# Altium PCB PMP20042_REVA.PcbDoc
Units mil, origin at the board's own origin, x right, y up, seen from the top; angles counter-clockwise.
Board outline 2260 x 1800 mil, 4 copper layers (Top Layer, Signal Layer 1, Signal Layer 2, Bottom Layer), stack 61.2 mil thick; 80 components, 41 nets, 195 pads, 85 vias.
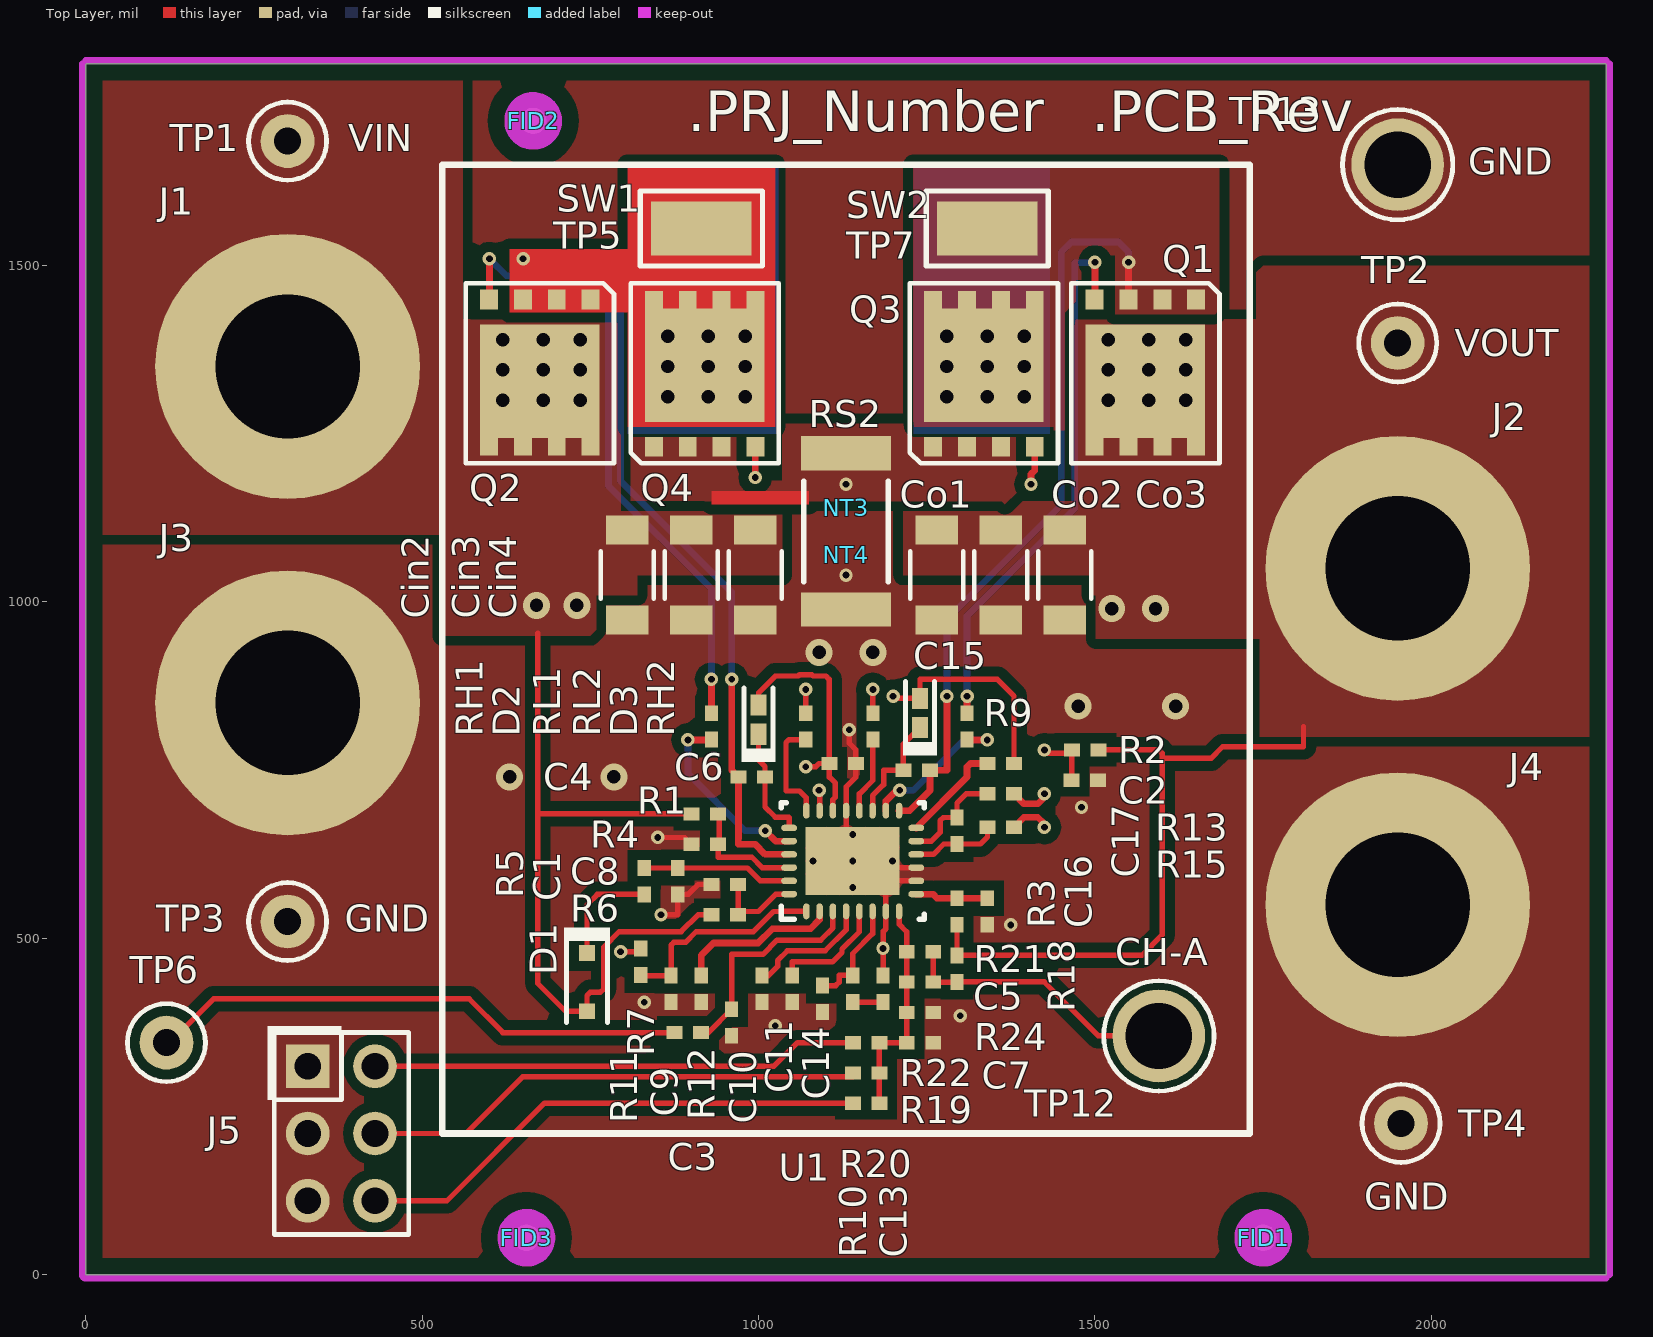
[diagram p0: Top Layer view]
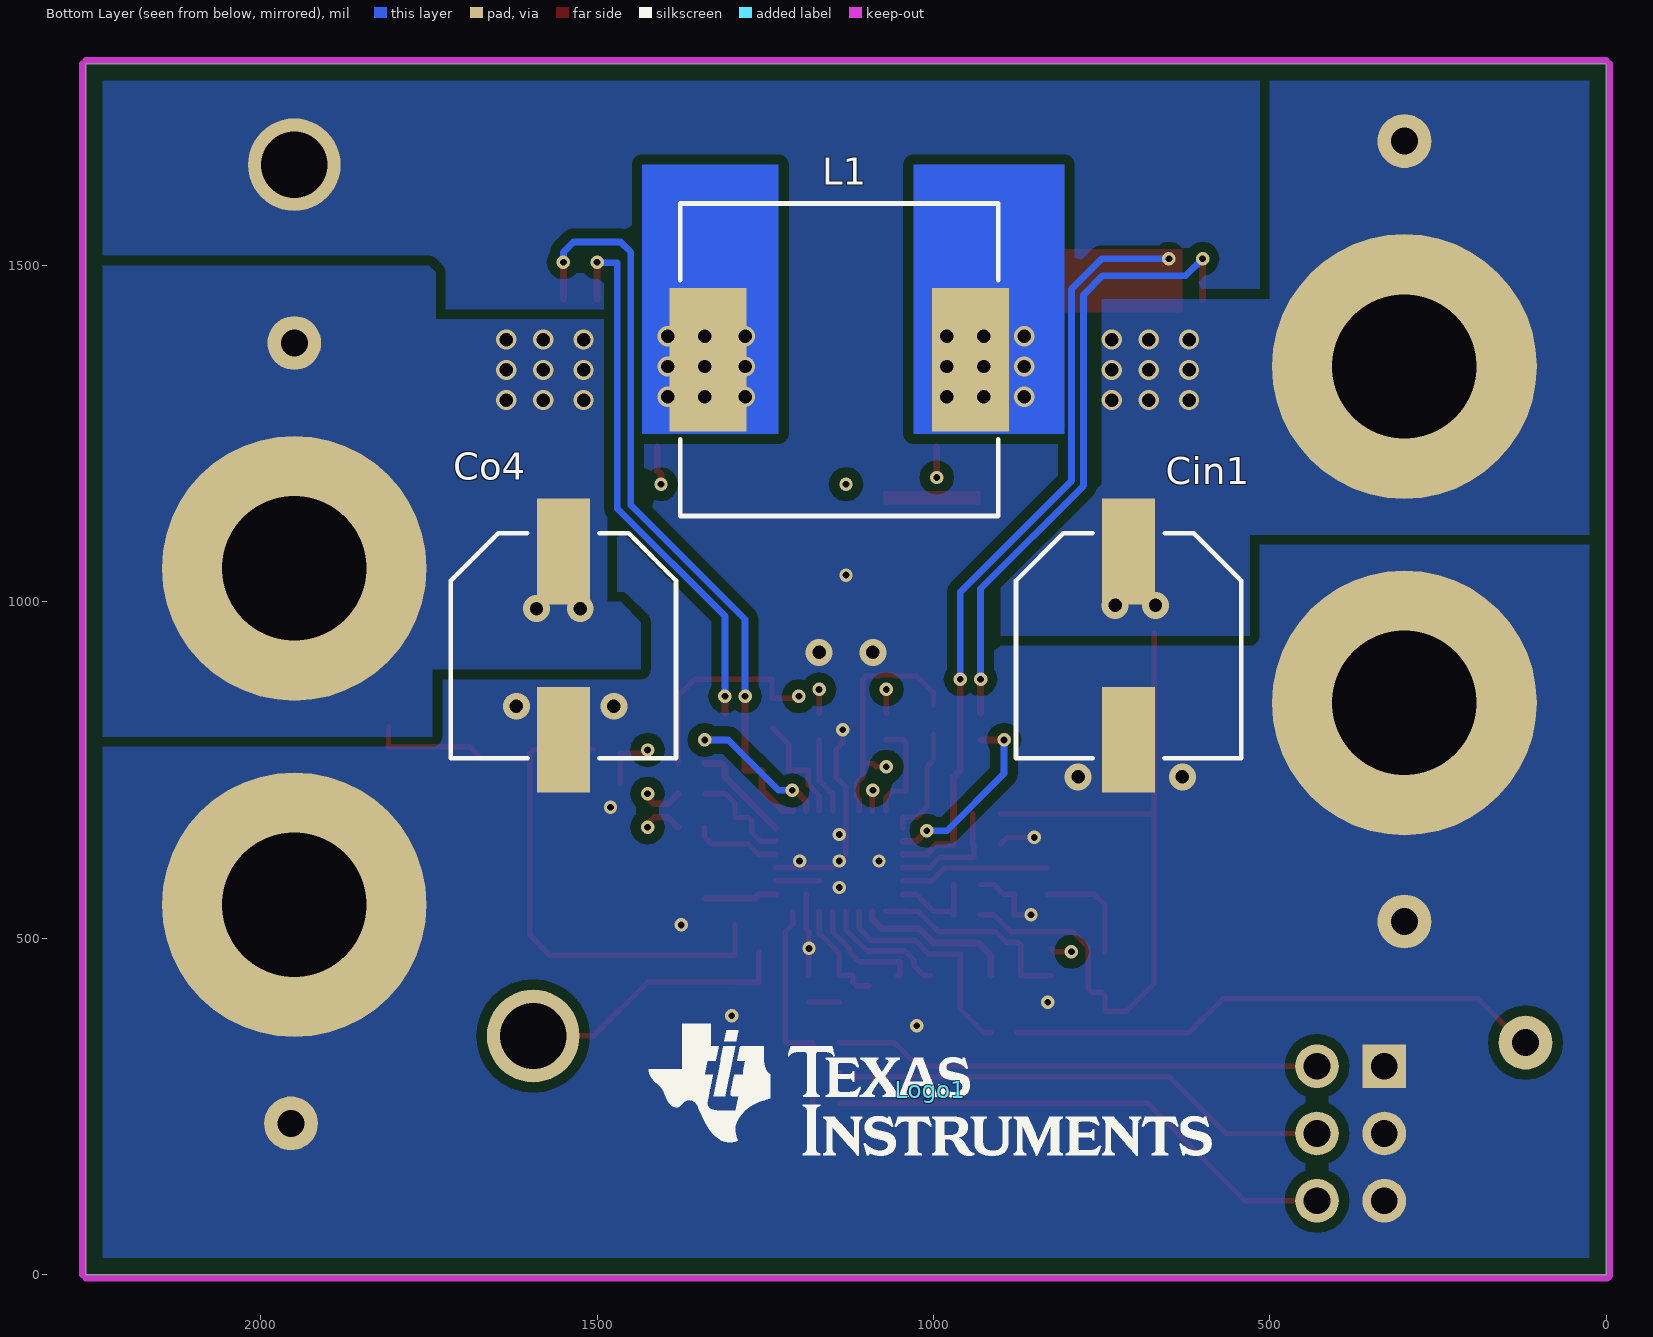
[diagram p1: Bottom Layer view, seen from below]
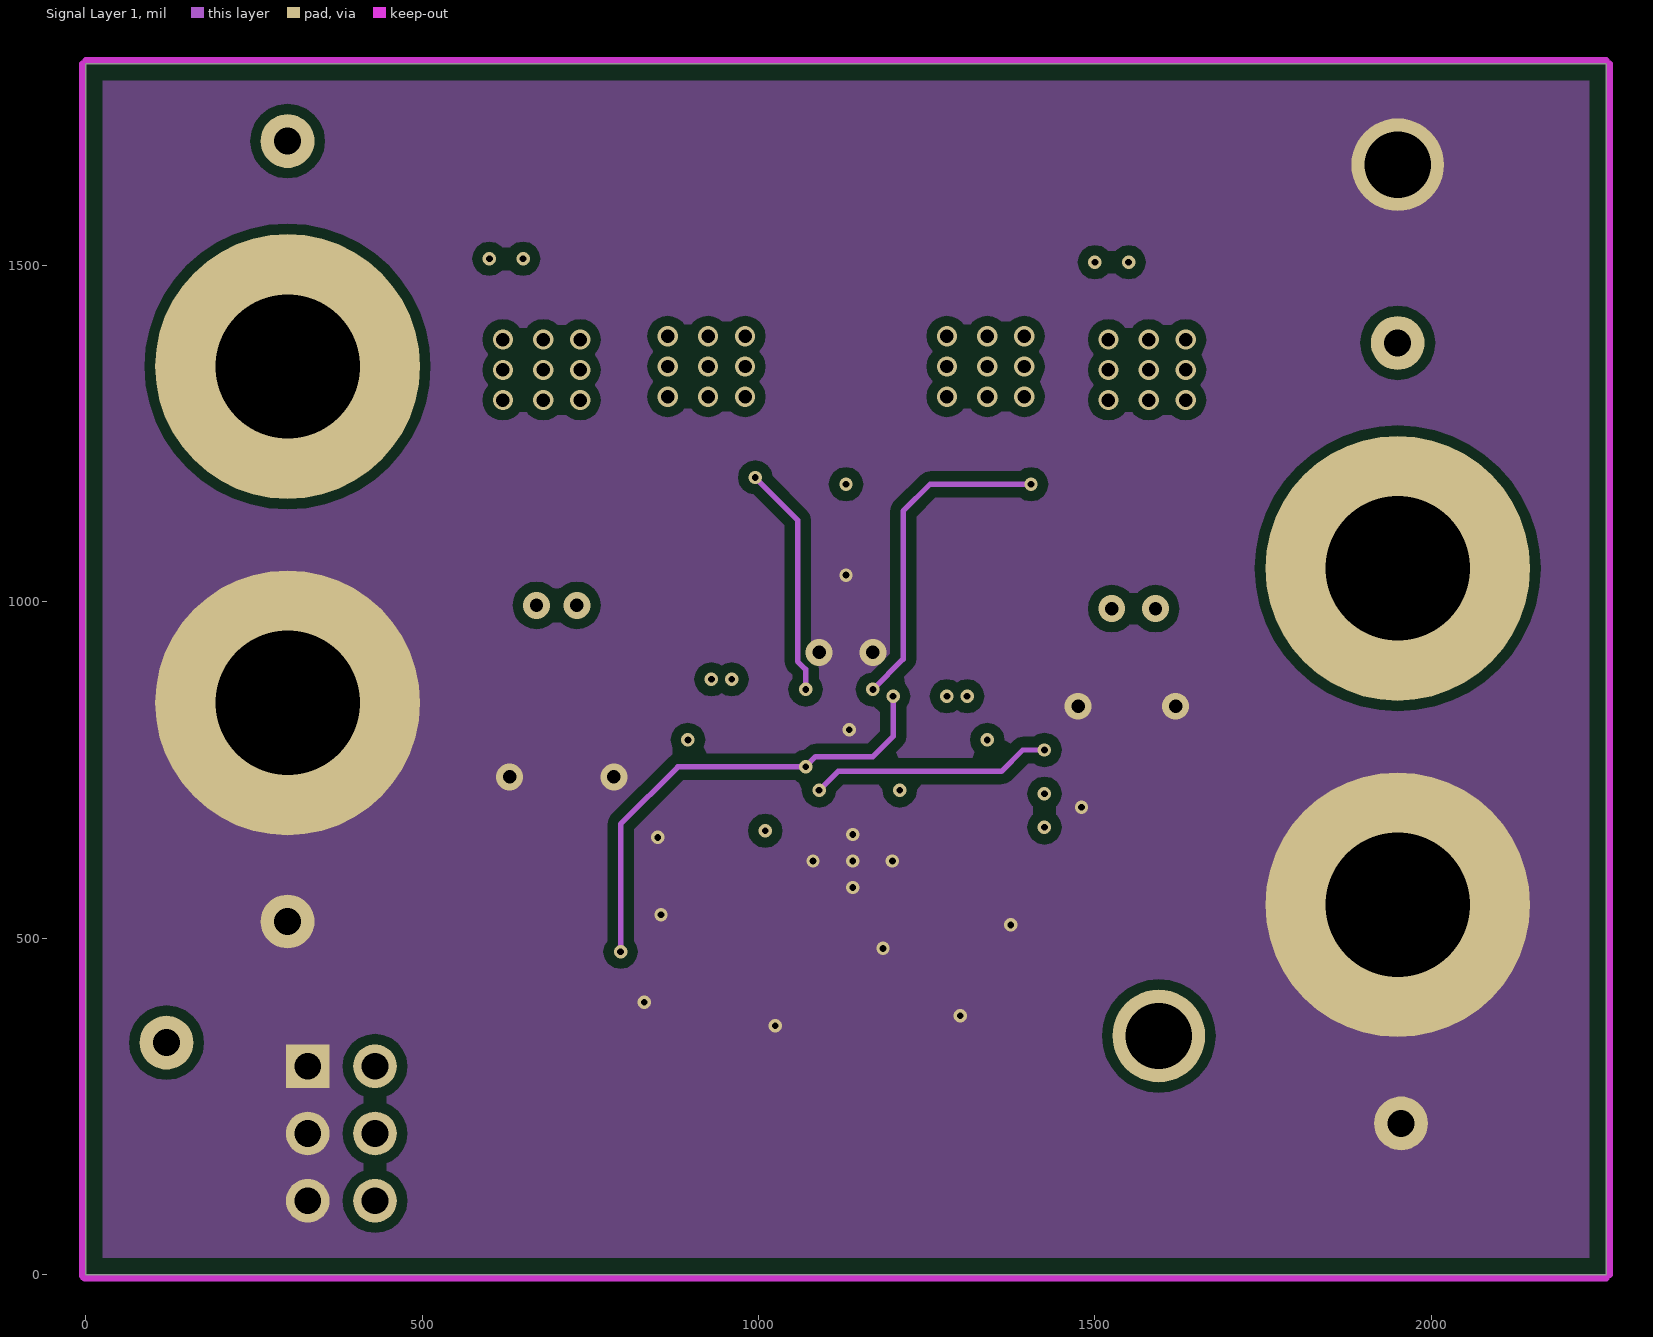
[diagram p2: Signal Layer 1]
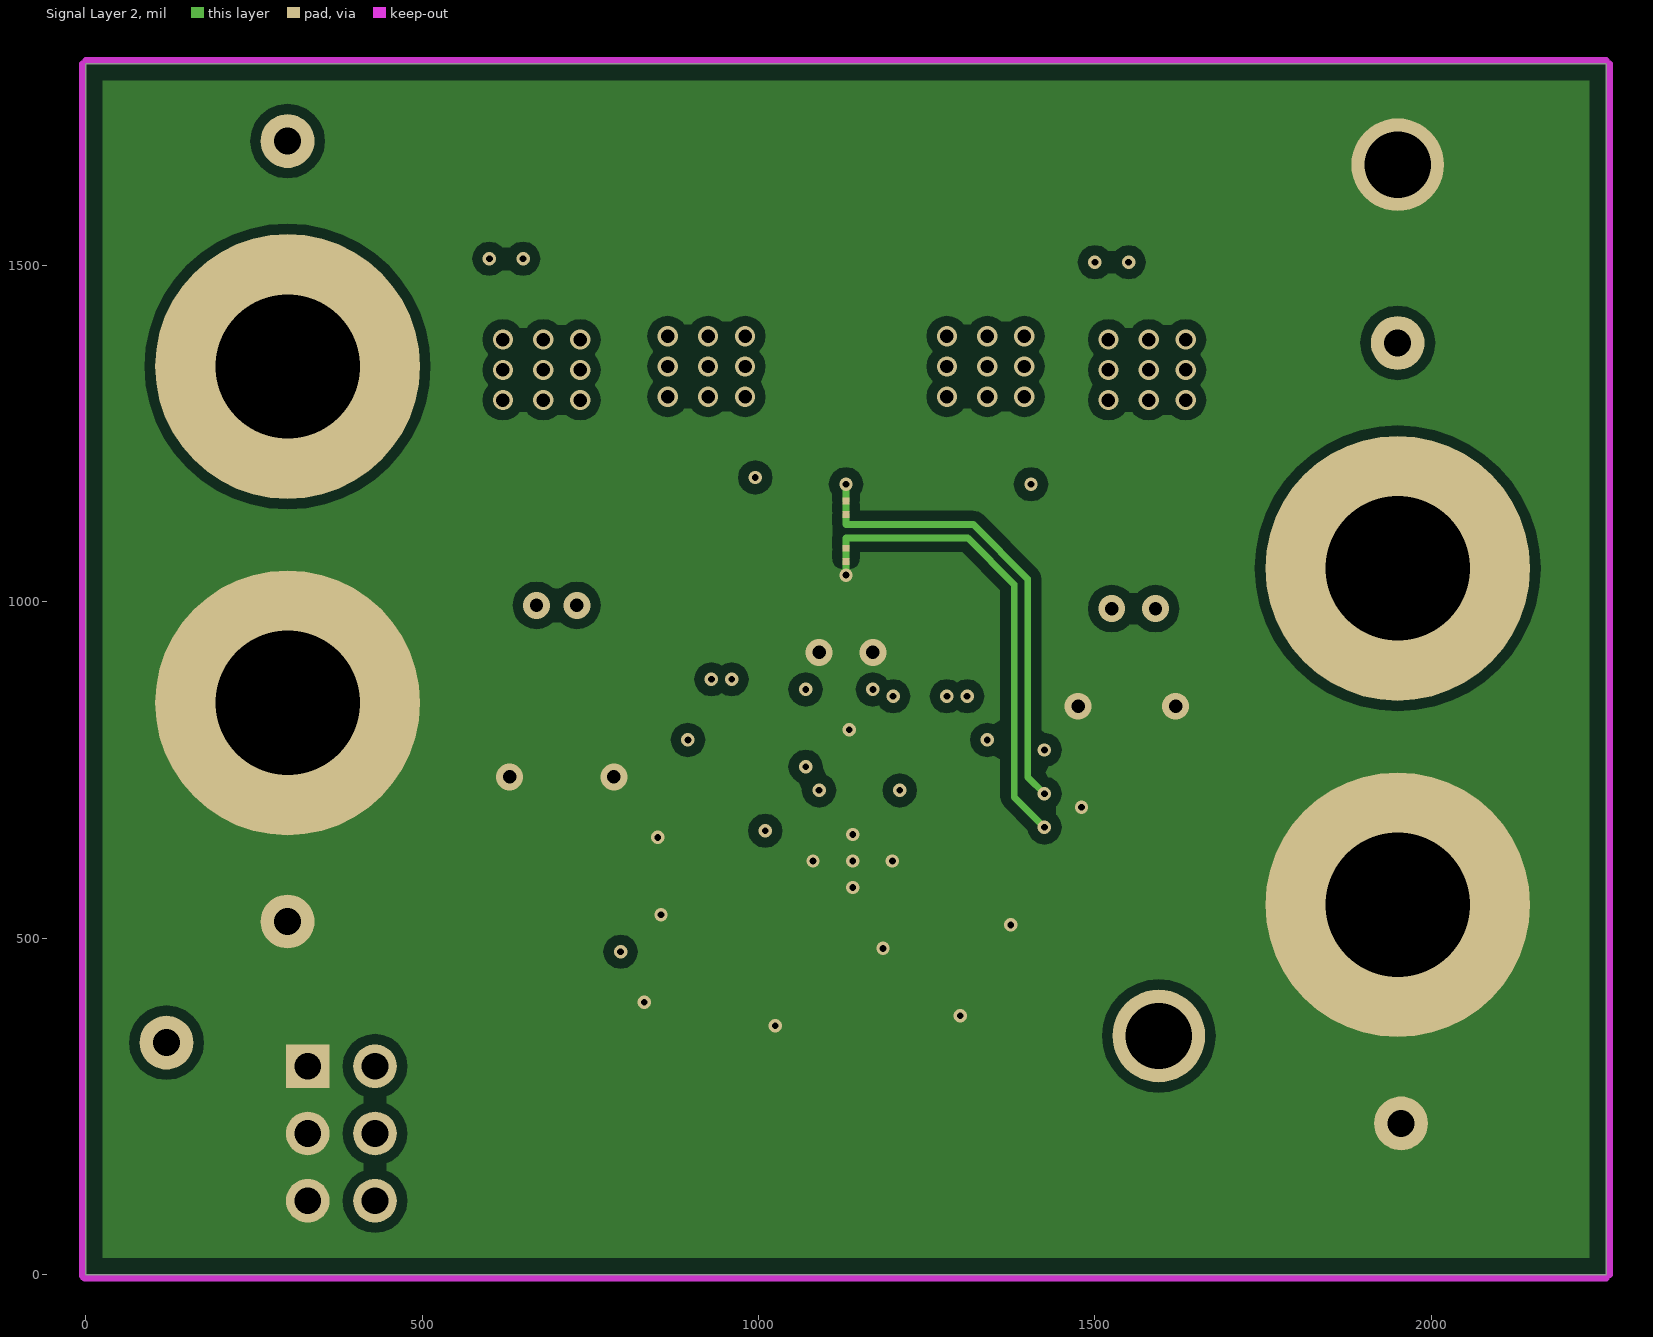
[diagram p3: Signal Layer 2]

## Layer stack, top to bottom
Top Solder: solder mask 0.4, Solder Resist, Dk 3.5
Top Layer: signal copper 2.8
Dielectric1: core 20, FR-4, Dk 4.8
Signal Layer 1: signal copper 1.4
Dielectric 2: prepreg 12.8, Dk 4.2
Signal Layer 2: signal copper 1.4
Dielectric 3: core 20, FR-4, Dk 4.8
Bottom Layer: signal copper 2.8
Bottom Solder: solder mask 0.4, Solder Resist, Dk 3.5

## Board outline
0,0 2260,0 2260,1800 0,1800

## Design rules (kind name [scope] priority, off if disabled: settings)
AcuteAngle [All] p1: minimum=4.50000000000000E+0001 checktracksonly=FALSE
AssemblyTestPointUsage [All] p1: valid=2
Clearance Clearance_Keepouts [((IsTrack Or IsArc) And Not InPoly) And IsFree and IsKeepOut vs ((IsTrack Or IsArc) And Not InPoly) And IsFree and IsKeepOut] p1: gap=0
Clearance Clearance_BoardEdge_MountingHoles [OnCopper and InComponentClass('Mounting Holes') vs IsKeepOut] p2: gap=40
Clearance Clearance_BoardEdge_Poly [OnCopper and InPoly vs IsKeepOut] p3: gap=25
Clearance Clearance_BoardEdge [OnCopper and Not InComponentClass('Logo') and not InComponentClass('FiducialMark') and not InRegion(1000,500,4000,800) and Not IsKeepout vs IsKeepOut] p4: gap=75
Clearance Clearance_Poly [InPolygon] p5: gap=15
Clearance [All] p6: gap=7.87
ComponentClearance ComponentClearance_Nettie [HasFootprint('Net-Tie_10mil')] p1: gap=0 collisioncheckmode=3 verticalgap=0 showdistances=FALSE
ComponentClearance ComponentClearance_MountingHoles_FiducialMarks [InComponentClass('Mounting Holes') vs InComponentClass('FiducialMark')] p2: gap=50 collisioncheckmode=3 verticalgap=10 showdistances=FALSE
ComponentClearance ComponentClearance_Shunt [InComponentClass('Header') vs InComponentClass('Shunt')] p3: gap=0 collisioncheckmode=3 verticalgap=0 showdistances=FALSE
ComponentClearance ComponentClearance_Logo [InComponentClass('Logo')] p4: gap=50 collisioncheckmode=3 verticalgap=10 showdistances=FALSE
ComponentClearance ComponentClearance_ScrewToNut [(HasFootprint('NY PMS 440 0025 PH')) vs (HasFootprint('Keystone_1902C'))] p5: gap=5 collisioncheckmode=3 verticalgap=10 showdistances=FALSE
ComponentClearance ComponentClearance_MountingHoles [InComponentClass('Mounting Holes')] p6: gap=250 collisioncheckmode=3 verticalgap=100000 showdistances=FALSE
ComponentClearance ComponentClearance_SmallPassives [HasFootprint('0201*') or HasFootprint('0402*') or HasFootprint('0508') or HasFootprint('0603*') or HasFootprint('0612') or HasFootprint('0805*') or HasFootprint('0815*') or HasFootprint('0830*') or HasFootprint('1206*') or HasFootprint('1210*') or HasFootprint('1808*') or HasFootprint('1812*') or HasFootprint('1825*') or HasFootprint('2010*') or HasFootprint('2220*') or HasFootprint('2225*') or HasFootprint('2512*') or HasFootprint('2728*') or HasFootprint('3518*') vs HasFootprint('0201*') or HasFootprint('0402*') or HasFootprint('0508') or HasFootprint('0603*') or HasFootprint('0612') or HasFootprint('0805*') or HasFootprint('0815*') or HasFootprint('0830*') or HasFootprint('1206*') or HasFootprint('1210*') or HasFootprint('1808*') or HasFootprint('1812*') or HasFootprint('1825*') or HasFootprint('2010*') or HasFootprint('2220*') or HasFootprint('2225*') or HasFootprint('2512*') or HasFootprint('2728*') or HasFootprint('3518*')] p7: gap=20 collisioncheckmode=3 verticalgap=10 showdistances=FALSE
ComponentClearance ComponentClearance_THtoSMT [IsThruComponent vs IsSMTComponent] p8: gap=100 collisioncheckmode=3 verticalgap=30 showdistances=FALSE
ComponentClearance ComponentClearance_THtoTH [IsThruComponent vs IsThruComponent] p9: gap=100 collisioncheckmode=3 verticalgap=30 showdistances=FALSE
ComponentClearance [All] p10: gap=40 collisioncheckmode=3 verticalgap=10 showdistances=FALSE
DiffPairsRouting [All] p1: maxlimit=100 minlimit=10 mostfreqgap=10 toplayer_minwidth=10 toplayer_maxwidth=15 toplayer_prefwidth=15 midlayer1_minwidth=10 midlayer1_maxwidth=15 midlayer1_prefwidth=15 midlayer2_minwidth=10 midlayer2_maxwidth=15 midlayer2_prefwidth=15 bottomlayer_minwidth=10 bottomlayer_maxwidth=15 bottomlayer_prefwidth=15 maxuncoupledlength=1000
FabricationTestPointUsage TestPointUsage [All] p1: valid=2 allowmultiple=FALSE
FabricationTestpoint Testpoint [All] p1: side=3 testpointundercomponent=TRUE minsize=40 maxsize=100 preferedsize=60 minholesize=0 maxholesize=40 preferedholesize=32 testpointgrid=1 allowsidetop=TRUE allowsidebottom=TRUE usegrid=TRUE gridtolerance=0.01
FanoutControl Fanout_LCC [IsLCC] p1: bgadir=Out bgaviamode=Centered fanoutstyle=Auto fanoutdirection=Alternating viagrid=1 // Fanout_LCC (Default Rule)
FanoutControl Fanout_BGA [IsBGA] p2: bgadir=Out bgaviamode=Centered fanoutstyle=Auto fanoutdirection=Alternating viagrid=1 // Fanout_BGA (Default Rule)
FanoutControl Fanout_Default [All] p4: bgadir=Out bgaviamode=Centered fanoutstyle=Auto fanoutdirection=Alternating viagrid=1 // Fanout_Default (Default Rule)
FanoutControl Fanout_Small [(CompPinCount < 5)] p5: bgadir=Out bgaviamode=Centered fanoutstyle=Auto fanoutdirection=OutThenIn viagrid=1 // Fanout_Small (Default Rule)
HoleSize [All] p1: absolutevalues=TRUE maxlimit=251 minlimit=8 maxpercent=80.000 minpercent=20.000
MinimumAnnularRing MinimumAnnularRing_ThermalPadVias [IsVia and InAnyComponent] p1: minimumring=5
MinimumAnnularRing [All] p2: minimumring=5
MinimumSolderMaskSliver MinimumSolderMaskSliver_Logo [InComponentClass('Logo') vs InComponentClass('Logo')] p1: minsoldermaskwidth=0.7
MinimumSolderMaskSliver [All] p2: minsoldermaskwidth=3.94
PlaneConnect [All] p1: planeconnectstyle=Direct reliefexpansion=10 reliefentries=4 reliefconductorwidth=10 reliefairgap=10
PolygonConnect [All] p1: connectstyle=Direct reliefconductorwidth=10 reliefentries=4 polygonreliefangle="90 Angle" airgapwidth=10
RoutingVias ThermalPadVias [IsVia and InAnyComponent] p1: holewidth=7.87 width=19.68 viastyle="Through Hole" minholewidth=7.87 minwidth=19.68 maxholewidth=12.99 maxwidth=23.62
RoutingVias [All] p2: holewidth=16 width=34 viastyle="Through Hole" minholewidth=7.87 minwidth=20 maxholewidth=40 maxwidth=65
SilkToBoardRegionClearance [Not ((IsComment or IsDesignator) And (Hide <> 'False')) and not InRegion(1000,500,4000,800)] p1:
SilkToSilkClearance SilkToSilkClearance_Pb-FreeLogo [(HasFootprint('Pb-Free_Overlay_Medium') OR HasFootprint('Pb-Free_Overlay_Small')) vs (HasFootprint('Pb-Free_Overlay_Medium') OR HasFootprint('Pb-Free_Overlay_Small'))] p1: silktosilkclearance=0
SilkToSilkClearance [All] p2: silktosilkclearance=4
SilkToSolderMaskClearance SilkToComonentPadClearance [IsPad and InAnycomponent] p1: minsilkscreentomaskgap=5 clearancetoexposedcopper=TRUE
SilkToSolderMaskClearance "Silk to Solder Mask Opening" [All] p2: minsilkscreentomaskgap=4 clearancetoexposedcopper=FALSE
SolderMaskExpansion [All] p1: expansion=1.97
UnpouredPolygon [All] p1: allowunpoured=FALSE
Width [All] p1: maxlimit=100 minlimit=6 preferedwidth=10 checkconnectedcopper=TRUE
14 further rules are at their usual default settings.

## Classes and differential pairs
component class PMP20042_REVA: C1 C2 C3 C4 C5 C6 C7 C8 C9 C10 C11 C13 C14 C15 C16 C17 Cin1 Cin2 Cin3 Cin4 Co1 Co2 Co3 Co4 Co6 D1 D2 D3 J1 J2 J3 J4 J5 L1 NT3 NT4 Q1 Q2 Q3 Q4 R1 R2 R3 R4 R5 R6 R7 R9 R10 R11 R12 R13 R15 R18 R19 R20 R21 R22 R24 RH1 RH2 RL1 RL2 RS2 TP1 TP2 TP3 TP4 TP5 TP6 TP7 TP12 TP13 U1
component class Header: J5
component class Logo: Logo1
component class PMP20042_REVA_Hardware: FID1 FID2 FID3 Logo1 ZZ2 ZZ3 ZZ4
component class FiducialMark: FID1 FID2 FID3
component class AssemblyNote: ZZ2 ZZ3 ZZ4
differential pair HDRV2: +HDRV2_P -HDRV2_N
differential pair HDRV1: +HDRV1_P -HDRV1_N
differential pair CS: +CS_P -CS_N

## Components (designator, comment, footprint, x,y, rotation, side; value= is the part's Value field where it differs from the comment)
C1 "C1005X5R1E224M050BC" 0402L 880,585 r270 top
C2 "C1005X5R1E224M050BC" 0402L 1485,735 r0 top
C3 "CC0402KRX7R9BB101" 0402L 895,360 r0 top
C4 "GRM155R71E104KE14D" 0402L 990,740 r180 top
C5 "C1005X7R1E223K" 0402L 1240,435 r180 top
C6 "C1005X5R1C105K050BC" 0402L 1125,760 r0 top
C7 "GCM155R71H104KE02D" 0402L 1240,345 r0 top
C8 "C1005X5R1E224M050BC" 0402L 950,580 r0 top
C9 "CRCW04020000Z0ED" 0402L 915,425 r270 top
C10 "CC0402KRX7R9BB101" 0402L 1005,425 r270 top
C11 "C1005X7R1H473K050BB" 0402L 1050,425 r270 top
C13 "C1005X7R1E223K" 0402L 1185,425 r90 top
C14 "C1005X7R1H221K" 0402L 1095,410 r270 top
C15 "GRM155R71E104KE14D" 0402L 1235,750 r180 top
C16 "C1005X5R1E224M050BC" 0402L 1340,540 r270 top
C17 "C1005X7R1H221K" 0402L 1295,660 r270 top
Cin1 "EEE-FK1J680UP" SM_RADIAL_F 710,935 r270 bottom
Cin2 "C3216X7R1V106M160AC" 1206_190 805,1040 r270 top
Cin3 "C3216X7R1V106M160AC" 1206_190 900,1040 r270 top
Cin4 "C3216X7R1V106M160AC" 1206_190 995,1040 r270 top
Co1 "C3216X7R1V106M160AC" 1206_190 1265,1040 r270 top
Co2 "C3216X7R1V106M160AC" 1206_190 1360,1040 r270 top
Co3 "C3216X7R1V106M160AC" 1206_190 1455,1040 r270 top
Co4 "EEE-FK1J680UP" SM_RADIAL_F 1550,935 r270 bottom
D1 "BAT54HT1G" sod-323 745,435 r270 top
D2 "BAS516,115" SOD-523 1000,825 r90 top
D3 "BAS516,115" SOD-523 1240,835 r90 top
FID1 "Fiducial" Fiducial10-20 1750,55 r0 top
FID2 "Fiducial" Fiducial10-20 665,1715 r0 top
FID3 "Fiducial" Fiducial10-20 655,55 r0 top
J1 "VIN" Keystone_575-4 300,1350 r0 top
J2 "VOUT" Keystone_575-4 1950,1050 r0 top
J3 "GND" Keystone_575-4 300,850 r0 top
J4 "GND" Keystone_575-4 1950,550 r0 top
J5 "PEC03DAAN" SULLINS_PEC03DAAN 380,210 r270 top
L1 "7443320470" WE-HCC_1210 1140,1360 r0 bottom
Logo1 "Texas Instruments" TI_Stacked_Overlay_Small 1005,275 r180 bottom
NT3 "Net-Tie" Net-Tie_10mil 1130,1140 r270 top net-tie
NT4 "Net-Tie" Net-Tie_10mil 1130,1070 r90 top net-tie
Q1 "CSD18504Q5A" TRANS_NexFET_Q5A 1575,1340 r270 top
Q2 "CSD18504Q5A" TRANS_NexFET_Q5A 675,1340 r270 top
Q3 "CSD18504Q5A" TRANS_NexFET_Q5A 1335,1340 r90 top
Q4 "CSD18504Q5A" TRANS_NexFET_Q5A 920,1340 r90 top
R1 "CRCW040271K5FKED" 0402L 920,685 r180 top
R2 "CRCW040210R0JNED" 0402L 1485.84,780.1 r0 top
R3 "CRCW040210R0JNED" 0402L 1295,540 r270 top
R4 "CRCW040246K4FKED" 0402L 920,640 r0 top
R5 "CRCW040210R0JNED" 0402L 830,585 r270 top
R6 "CRCW040210R0JNED" 0402L 950,535 r0 top
R7 "CRCW04020000Z0ED" 0402L 825,465 r90 top
R9 "CRCW040220K0JNED" 0402L 1360,760 r0 top
R10 "CRCW04023K32FKED" 0402L 1140,425 r90 top
R11 "CRCW040249K9FKED" 0402L 870,425 r90 top
R12 "CRCW040264K9FKED" 0402L 960,375 r90 top
R13 "CRCW0402100RFKED" 0402L 1360,715 r0 top
R15 "CRCW0402100RFKED" 0402L 1360,665 r0 top
R18 "CRCW040247R0JNED" 0402L 1295,455 r270 top
R19 "CRCW04026K81FKED" 0402L 1160,300 r0 top
R20 "CRCW040210K0FKED" 0402L 1160,255 r0 top
R21 "CRCW040249K9FKED" 0402L 1240,480 r0 top
R22 "CRCW04027K87FKED" 0402L 1160,345 r0 top
R24 "CRCW04029K53FKED" 0402L 1240,390 r180 top
RH1 "CRCW04023R00JNED" 0402L 930,815 r90 top
RH2 "CRCW04020000Z0ED" 0402L 1310,815 r270 top
RL1 "CRCW04020000Z0ED" 0402L 1070,815 r90 top
RL2 "CRCW04020000Z0ED" 0402L 1170,815 r270 top
RS2 "ERJ-M1WSF6M0U" 2512 1130,1105 r90 top
TP1 "VIN" Keystone5000 300,1685 r0 top
TP2 "VOUT" Keystone5000 1950,1385 r0 top
TP3 "GND" Keystone5001 300,525 r0 top
TP4 "GND" Keystone5001 1955,225 r0 top
TP5 "SW1" Keystone_5019 915,1555 r0 top
TP6 "SYNC" Keystone5002 120,345 r0 top
TP7 "SW2" Keystone_5019 1340,1555 r0 top
TP12 "CH-A" Keystone1598-2 1595,355 r0 top
TP13 "GND" Keystone1598-2 1950,1650 r0 top
U1 "LM5175RHFR" RHF0028A 1140,615 r90 top
ZZ2 "These assemblies are ESD sensitive, ESD precautions shall be observed." AssemblyNote 185,3829.11 r0 top
ZZ3 "These assemblies must be clean and free from flux and all contaminants. Use of no clean flux is not acceptable." AssemblyNote 185,3740.56 r0 top
ZZ4 "These assemblies must comply with workmanship standards IPC-A-610 Class 2, unless otherwise specified." AssemblyNote 185,3652 r0 top

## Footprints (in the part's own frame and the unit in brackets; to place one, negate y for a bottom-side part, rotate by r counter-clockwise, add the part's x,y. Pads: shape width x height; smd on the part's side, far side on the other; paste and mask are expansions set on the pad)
0402L [mm] "0402 from SM-752 data"
  rect 0.6x0.5 smd: 1(-0.5,0) 2(0.5,0)
  body extent -0.55,-0.3 0.55,0.3, height 0.6
1206_190 [mm] "1206_190"
  rect 1.1x1.6 smd: 1(-1.7,0) 2(1.7,0)
  silkscreen extent -0.9,-1 0.9,1, body extent -1.75,-0.95 1.75,0.95, height 1.9
2512 [mm] "Chip Resistor, Body 6.3x3.2mm, IPC Medium Density"
  rect 1.3x3.4 smd: 1(-2.95,0) 2(2.95,0)
  silkscreen extent -1.9,-1.6 1.9,1.6, body extent -3.22,-1.67 3.22,1.67, height 0.71
AssemblyNote [mil] "Assembly Note"
Fiducial10-20 [mm]
  round 1 smd mask+0.5: 1(0,0)
  Top Layer keep-out circle w1.178: c0,0 r0.5
Keystone1598-2 [mm] "Triple Turret"
  round 3.5 hole 2.5: 1(0,0)
  silkscreen extent -2.08,-2.08 2.08,2.08, body extent -1.6,-1.6 1.59,1.6, height 7.72
Keystone5000 [mil] "For Keystone 500x miniature loop terminals"
  round 80 hole 40: 1(0,0)
  silkscreen extent -58,-58 58,58, body extent -49,-49 49,49, height 182
Keystone5001 [mil] "For Keystone 500x miniature loop terminals"
  round 80 hole 40: 1(0,0)
  silkscreen extent -58,-58 58,58, body extent -49,-49 49,49, height 182
Keystone5002 [mil] "For Keystone 500x miniature loop terminals"
  round 80 hole 40: 1(0,0)
  silkscreen extent -58,-58 58,58, body extent -49,-49 49,49, height 182
Keystone_575-4 [mm] "Banana Jack"
  round 10 hole 5.45: 1(0,0)
  body extent -3.95,-3.95 3.92,3.93, height 2.36
Keystone_5019 [mm] "Test Point, Miniature, SMT"
  rect 3.8x2.03 smd: 1(0,0)
  silkscreen extent -2.31,-1.42 2.31,1.42, body extent -1.9,-1.02 1.9,1.02, height 2.29
Net-Tie_10mil [mil] "10mil net tie, no solder mask opening, no solder paste"
  rect 10x10 on Mid2 paste-5 mask-5: 1(-10,0) 2(10,0)
  Signal Layer 2 region: -6,5 6,5 6,-5 -6,-5
RHF0028A [mm] "QFN, 28-Leads, Body 5x4mm, Pitch 0.5mm, Thermal Pad 3.55x2.55mm"
  oval 0.6x0.24 smd: 1(-1.9,1.75) 2(-1.9,1.25) 3(-1.9,0.75) 4(-1.9,0.25) 5(-1.9,-0.25) 6(-1.9,-0.75) 7(-1.9,-1.25) 8(-1.9,-1.75) 15(1.9,-1.75) 16(1.9,-1.25) 17(1.9,-0.75) 18(1.9,-0.25) 19(1.9,0.25) 20(1.9,0.75) 21(1.9,1.25) 22(1.9,1.75)
  oval 0.24x0.6 smd: 9(-1.25,-2.4) 10(-0.75,-2.4) 11(-0.25,-2.4) 12(0.25,-2.4) 13(0.75,-2.4) 14(1.25,-2.4) 23(1.25,2.4) 24(0.75,2.4) 25(0.25,2.4) 26(-0.25,2.4) 27(-0.75,2.4) 28(-1.25,2.4)
  rect 2.55x3.55 smd paste-3.55: 29(0,0)
  silkscreen extent -2.2,-2.7 2.2,2.7, body extent -2.07,-2.57 2.07,2.57, height 1.01
SM_RADIAL_F [mm] "8 x 10.2mm:  Panasonic F"
  rect 4x2 smd: 1(-3.55,0) 2(3.55,0)
  silkscreen extent -4.25,-4.25 4.25,4.25, body extent -4.26,-4.26 4.26,4.26, height 10.5
sod-323 [mm] "NXP recommended land pattern"
  rect 0.6x0.6 smd paste-0.05: 1(-1.1,0) 2(1.1,0)
  silkscreen extent -2.06,-0.86 1.53,0.86, body extent -1.3,-0.67 1.3,0.68, height 1.1
SOD-523 [mm] "NXP Semiconductor recommended land pattern, nominal STEP model"
  rect 0.8x0.6 smd paste-0.05: 1(-0.55,0) 2(0.55,0)
  silkscreen extent -1.6,-0.64 1.2,0.63, body extent -0.8,-0.4 0.8,0.4, height 0.72
SULLINS_PEC03DAAN [mm] "SULLINS"
  rect 1.65x1.65 hole 1.016 mask+0: 1(-2.54,-1.27)
  round 1.65 hole 1.016 mask+0: 2(-2.54,1.27) 3(0,-1.27) 4(0,1.27) 5(2.54,-1.27) 6(2.54,1.27)
  silkscreen extent -4.06,-2.79 3.81,2.54, body extent -3.81,-2.54 3.81,2.54, height 8.38
TI_Stacked_Overlay_Small [mil]
  silkscreen extent -418,-98 418,98
TRANS_NexFET_Q5A [mm] "TI recommended land pattern (nominal) M0139-01"
  rect 0.75x0.675 smd paste-0.1 mask+0.051: 1(-2.776,1.917) 2(-2.776,0.639) 3(-2.776,-0.639) 4(-2.776,-1.917)
  rect 0.655x0.675 smd paste-0.1 mask+0.051: 5(2.776,-1.917) 6(2.776,-0.639) 7(2.776,0.639) 8(2.776,1.917)
  rect 4.295x4.51 smd paste-2.2 mask+0.051: 9(0.301,0)
  silkscreen extent -3.4,-2.8 3.4,2.8, body extent -3.05,-2.5 3.05,2.5, height 1.11
WE-HCC_1210 [mm] "WURTH"
  rect 2.9x5.4 smd: 1(-4.95,0) 2(4.95,0)
  silkscreen extent -6,-5.9 6,5.9, body extent -6,-5.85 6,5.85, height 10

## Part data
C1 C2 C8 C16: "CAP, CERM, 0.22 µF, 25 V, +/- 20%, X5R, 0402"
C3 C10: "CAP, CERM, 100 pF, 50 V, +/- 10%, X7R, 0402"
C4 C15: "CAP, CERM, 0.1 µF, 25 V, +/- 10%, X7R, 0402"
C5 C13: "CAP, CERM, 0.022 µF, 25 V, +/- 10%, X7R, 0402"
C6: "CAP, CERM, 1 µF, 16 V, +/- 10%, X5R, 0402"
C7: "CAP, CERM, 0.1 µF, 50 V, +/- 10%, X7R, AEC-Q200 Grade 1, 0402"
C9 R7 RH2 RL1 RL2: "RES, 0, 5%, 0.063 W, 0402"
C11: "CAP, CERM, 0.047 µF, 50 V, +/- 10%, X7R, 0402"
C14 C17: "CAP, CERM, 220 pF, 50 V, +/- 10%, X7R, 0402"
Cin1 Co4: "CAP, AL, 68 µF, 63 V, +/- 20%, 0.65 ohm, SMD"
Cin2 Cin3 Cin4 Co1 Co2 Co3: "CAP, CERM, 10 µF, 35 V, +/- 20%, X7R, 1206_190"
D1: "Diode, Schottky, 30V, 0.2A, SOD-323"
D2 D3: "Diode, Switching, 100V, 0.25A, SOD-523"
FID1 FID2 FID3: "Fiducial mark.  There is nothing to buy or mount."
J1 J2 J3 J4: library part 575-4, "Standard Banana Jack, Uninsulated, 5.5mm"
J5: "Header, 100mil, 3x2, Tin, TH"
L1: "Inductor, Shielded Drum Core, Ferrite, 4.7 µH, 15.5 A, 0.0064 ohm, SMD"
Logo1: library part TI_Logo, "Texas Instrument Corporate Signature"
NT3 NT4: "Single point connection between nets."
Q1 Q2 Q3 Q4: "MOSFET, N-CH, 40 V, 15 A, SON 5x6mm"
R1: "RES, 71.5 k, 1%, 0.063 W, 0402"
R2 R3 R5 R6: "RES, 10, 5%, 0.063 W, 0402"
R4: "RES, 46.4 k, 1%, 0.063 W, 0402"
R9: "RES, 20 k, 5%, 0.063 W, 0402"
R10: "RES, 3.32 k, 1%, 0.063 W, 0402"
R11 R21: "RES, 49.9 k, 1%, 0.063 W, 0402"
R12: "RES, 64.9 k, 1%, 0.063 W, 0402"
R13 R15: "RES, 100, 1%, 0.063 W, 0402"
R18: "RES, 47, 5%, 0.063 W, 0402"
R19: "RES, 6.81 k, 1%, 0.063 W, 0402"
R20: "RES, 10.0 k, 1%, 0.063 W, 0402"
R22: "RES, 7.87 k, 1%, 0.063 W, 0402"
R24: "RES, 9.53 k, 1%, 0.063 W, 0402"
RH1: "RES, 3.0, 5%, 0.063 W, 0402"
RS2: "RES, 0.006, 1%, 1 W, 2512"
TP1 TP2: library part 5000, "Test Point, TH, Miniature, Red"
TP3 TP4: library part 5001, "Test Point, TH, Miniature, Black"
TP5 TP7: library part 5019, "Test Point, Miniature, SMT"
TP6: library part 5002, "Test Point, Miniature, White, TH"
TP12 TP13: library part 1598-2, "Terminal, Turret, TH, Triple"
U1: "42-V Wide VIN Synchronous 4-Switch Buck-Boost Controller, RHF0028A"
ZZ2 ZZ3 ZZ4: library part AssemblyNote

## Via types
v1: diameter 20, hole 10, Top Layer to Bottom Layer, 39 vias
v2: diameter 30, hole 20, Top Layer to Bottom Layer, 36 vias
v3: diameter 40, hole 20, Top Layer to Bottom Layer, 10 vias

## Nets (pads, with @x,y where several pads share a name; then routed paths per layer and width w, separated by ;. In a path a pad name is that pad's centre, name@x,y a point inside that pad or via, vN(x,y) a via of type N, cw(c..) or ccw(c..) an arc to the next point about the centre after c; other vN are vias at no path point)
BIAS: C2.1 R2.1 U1.21 | length 476.6
  Top Layer w8: U1.21 v1@1090.79,719.21 ; v1(1425,780) 1430,775 1465.32,775 C2.1@1465.32,730
  Signal Layer 1 w8: v1(1090,720) 1118.14,748.14 1360.81,748.14 1392.67,780 v1(1425,780)
BOOT1: C4.1 D2.1 U1.23 | length 170.4
  Top Layer w8: D2.1 1000,765 1009.68,755.32 C4.1 1009.68,695.32 1025,680 1045,680 1045.51,679.49 U1.23 U1.23@1045,664.72
BOOT2: C15.2 D3.1 U1.17 | length 170
  Top Layer w8: U1.17 1169.53,712.08 1185.87,728.42 1185.87,750 C15.2 1215.31,788.66 D3.1
COMP: C14.1 R10.2 U1.6 | length 165.1
  Top Layer w8: C14.1 1114.68,429.68 1120,435 1120,445 1139.69,445 R10.2 1140,477.55 1169.53,507.08 U1.6
CS_N: NT4.2 R15.2 | length 733.9
  Top Layer w10: R15.2 1394.69,680 1415,680 1425,670 v1(1425,665)
  Signal Layer 2 w10: NT4.2 1130,1095 1311.06,1095 1380,1026.06 1380,710 v1(1425,665)
CS_P: NT3.2 R13.2 | length 708.8
  Top Layer w10: R13.2 1394.69,700 1415,700 1425,710 v1(1425,715)
  Signal Layer 2 w10: NT3.2 1130,1115 1319.35,1115 1400,1034.35 1400,740 v1(1425,715)
CTL_1: J5.6 R20.1 | length 770.4
  Top Layer w8: J5.6 536.82,110 681.82,255 R20.1
CTL_2: J5.4 R19.1 | length 751
  Top Layer w8: J5.4 565,210 649.13,294.13 1140.32,294.13 R19.1
CTL_3: J5.2 R22.1 | length 724.8
  Top Layer w8: J5.2 1022.92,310 1057.92,345 R22.1
DITH: C9.1 U1.2 | length 240.3
  Top Layer w10: C9.1 915,475 933.13,493.13 999.44,493.13 1020.66,514.34 1077.22,514.34 1090.79,527.91 U1.2
EN: R1.1 R4.2 U1.26 | length 176.5
  Top Layer w8: R4.2 940,639.69 940,620.56 990.02,620.56 1005.42,605.16 U1.26 ; R4.2@941.5,640 R1.1@941.5,685
FB: C5.2 C7.1 R19.2 R20.2 R21.1 R22.2 R24.2 U1.8 | length 330.6
  Top Layer w8: R20.2 R19.2 R22.2 C7.1 R21.1 1220.32,509.68 1208.9,521.1 U1.8
GND: C1.2 C2.2 C6.2 C7.2 C8.1 C9.2 C10.2 C11.2 C13.2 C14.2 C16.2 Cin1.2 Cin2.2 Cin3.2 Cin4.2 Co1.2 Co2.2 Co3.2 Co4.2 J3.1 J4.1 J5.1 J5.3 J5.5 NT4.1 R4.1 R11.1 R12.1 R24.1 RS2.1 TP3.1 TP4.1 TP13.1 U1.7 U1.10 U1.11 U1.19 U1.29 | length 653.8
  Top Layer w8: v1(850,650) 890.32,650 R4.1 ; v1(855,535) 880,535 C1.2 895.31,565.31 910,580 C8.1 ; U1.29@1130.16,624.84 U1.19 1130.16,725.16 1144.69,739.69 C6.2 1144.69,780.31 1135,790 v1(1135,810) ; U1.29@1149.84,605.16 U1.11 ; U1.29@1169.53,585.47 U1.10 ; C13.2 1185.4,445.09 1185.4,510.4 1189.21,514.21 U1.7 U1.29@1189.21,565.79
  Signal Layer 2 w10: v1(1130,1040) NT4.1
  other v1: 1025,370 1300,385 830,405 1185,485 1375,520 1140,575.63 1080.94,615 1140,615 1199.06,615 1140,654.37 1480,695
  other v3: 630,740 785,740 1475,845 1620,845 1090,925 1170,925
HDRV1_N: C4.2 L1.1 Q2.1 Q2.2 Q2.3 Q4.5 Q4.6 Q4.7 Q4.8 Q4.9 TP5.1 U1.25 | length 1203.3
  Top Layer w10: Q2.3@650,1449.47 v1(650,1510) ; v1(960,885) 960,750.31 C4.2 970.31,648.9 ; 970,648.58 970,640 994.64,640 1009.8,624.84 U1.25
  Bottom Layer w10: v1(650,1510) 750,1510 795,1465 795,1180 960,1015 v1(960,885)
  other v2: 865,1305 925,1305 980,1305 865,1350 925,1350 980,1350 865,1395 925,1395 980,1395
HDRV1_P: RH1.1 U1.24 | length 276.8
  Top Layer w10: v1(895,795) RH1.1@929.68,795 ; v1(1010,660) 1025.47,644.53 U1.24
  Bottom Layer w10: v1(895,795) 895,745 980,660 v1(1010,660)
HDRV2_N: C15.1 L1.2 Q1.1 Q1.2 Q1.3 Q3.5 Q3.6 Q3.7 Q3.8 Q3.9 TP7.1 U1.15 | length 1137.2
  Top Layer w10: U1.15 1224.8,689.8 1254.68,719.68 C15.1 1280,750 v1(1280,860) ; Q1.3@1550,1449.47 v1(1550,1505)
  Bottom Layer w10: v1(1280,860) 1280,974.28 1450,1144.28 1450,1520 1465,1535 1535,1535 1550,1520 v1(1550,1505)
  other v2: 1280,1305 1340,1305 1395,1305 1280,1350 1340,1350 1395,1350 1280,1395 1340,1395 1395,1395
HDRV2_P: RH2.2 U1.16 | length 232.5
  Top Layer w10: U1.16 1189.21,704.21 1205,720 v1(1210,720) ; RH2.2@1310.31,795 v1(1340,795)
  Bottom Layer w10: v1(1210,720) 1230,720 1305,795 v1(1340,795)
LDRV1: RL1.1 U1.22 | length 156.3
  Top Layer w8: RL1.1 1045.32,795.32 1040.87,790.87 1040.87,719.13 1060.87,719.13 1071.1,708.9 U1.22
LDRV2: RL2.2 U1.18 | length 113.9
  Top Layer w8: U1.18 1149.84,714.84 1170,735 RL2.2
MODE: R7.1 R11.2 U1.1 | length 311.6
  Top Layer w8: R7.1@825.63,444.69 R11.2 870,490 874.13,494.13 891.58,494.13 907.45,510 992.45,510 1022.45,540 1038.62,540 1038.82,540.2 U1.1
NetC3_1: C3.1 TP6.1 | length 802.9
  Top Layer w8: TP6.1 125,345 190,410 570,410 620,360 C3.1
NetC5_1: C5.1 R18.2 R21.2 TP12.1 | length 413.3
  Top Layer w8: R21.2 C5.1 R18.2@1294.69,435 ; R18.2 1424.69,435.31 1505,355 TP12.1
NetC13_1: C13.1 R10.1 | length 45
  Top Layer w8: R10.1 C13.1
NetC17_1: C17.1 R13.1 U1.13 | length 157.9
  Top Layer w8: U1.13 1257.08,644.53 1270,657.45 1270,675 1274.68,679.68 C17.1 1295,701.14 1308.86,715 R13.1
NetC17_2: C17.2 R15.1 U1.12 | length 130.7
  Top Layer w8: U1.12 1259.84,624.84 1275.31,640.31 C17.2 1329.69,640.31 1340.32,650.94 R15.1
NetD1_1: D1.1 R5.2 | length 163
  Top Layer w8: D1.1 745,550 760.31,565.31 R5.2
NetQ1_4: Q1.4 RH2.1 | length 819.8
  Top Layer w10: RH2.1 v1(1310,860) ; Q1.4@1500,1449.8 v1(1500,1505)
  Bottom Layer w10: v1(1310,860) 1310,979 1470,1139 1470,1504 v1@1499,1504
NetQ2_4: Q2.4 RH1.2 | length 944.6
  Top Layer w10: Q2.4@600,1449.8 v1(600,1510) ; RH1.2 v1(930,885)
  Bottom Layer w10: v1(600,1510) 625,1485 748.5,1485 777.13,1456.38 777.13,1172.6 930,1019.72 v1(930,885)
NetQ3_4: Q3.4 RL2.1 | length 583.5
  Top Layer w8: RL2.1 v1(1170,870)
  Top Layer w10: v1(1405,1175) 1405,1190 1410.49,1195.49 Q3.4
  Signal Layer 1 w8: v1(1170,870) 1215,915 1215,1135 1255,1175 v1(1405,1175)
NetQ4_4: Q4.4 RL1.2 | length 432.3
  Top Layer w8: RL1.2 v1(1070,870)
  Top Layer w10: v1(995,1185) 995,1230.2 Q4.4
  Signal Layer 1 w8: v1(995,1185) 1058.13,1121.87 1058.13,911.8 1070,899.92 v1(1070,870)
  Signal Layer 1 w10: v1(995,1185) v1@995,1190
PGOOD: R9.1 U1.14 | length 154.5
  Top Layer w10: U1.14 1234.49,664.49 1310,740 1310,755 1315,760 R9.1
SLOPE: C10.1 U1.4 | length 185.9
  Top Layer w8: C10.1 1014.68,444.68 1028.28,458.28 1028.28,466.94 1042.94,481.6 1099.04,481.6 1130.16,512.71 U1.4
SS: C11.1 U1.5 | length 175
  Top Layer w8: C11.1@1053.01,444.68 C11.1 1050,465 1110,465 1124.13,479.13 1124.13,484.13 1149.84,509.84 U1.5
SYNC: C3.2 R12.2 U1.3 | length 332.7
  Top Layer w8: C3.2 925.31,360 R12.2 960,476.25 1006.43,476.25 1027.65,497.47 1092.47,497.47 1110.47,515.47 U1.3
VCC: C6.1 D2.2 D3.2 R7.2 R9.2 U1.20 | length 1431.3
  Top Layer w8: v1(795,480) 820.31,480 R7.2 ; D2.2 1000,865 1025,890 1059.07,890 1060.94,891.87 1079.06,891.87 1080.93,890 1100,890 1105,885 1105,805 1105.32,804.68 C6.1 ; v1(1070,755) 1085,755 1090,760 C6.1 ; U1.20 1110.47,706.19 1114.28,710 1114.28,730.72 1105.32,739.68 C6.1 ; v1@1203.35,856.65 D3.2 1240,885 1355,885 1379.69,860.31 R9.2
  Signal Layer 1 w8: v1(795,480) 795,670 880,755 v1(1070,755) 1085,770 1170,770 1200,800 v1(1200,860)
VIN: Cin1.1 Cin2.1 Cin3.1 Cin4.1 D1.2 J1.1 Q2.5 Q2.6 Q2.7 Q2.8 Q2.9 R1.2 R6.1 TP1.1 | length 1133.8
  Top Layer w8: 671.69,953.31 671.69,685 ; R1.2 671.69,685 ; R6.1 910,535 885,510 793,510 770,487 770,425 765,420 750,420 745,415 D1.2 713.31,391.69 671.69,433.31 671.69,685
  other v2: 620,1300 680,1300 735,1300 620,1345 680,1345 735,1345 620,1390 680,1390 735,1390
  other v3: 670,995 730,995
VIN_IC: C1.1 R5.1 U1.27 | length 223.5
  Top Layer w8: R5.1 C1.1 983.45,604.68 1002.66,585.47 U1.27
VINSNS: C8.2 R6.2 U1.28 | length 131.5
  Top Layer w8: R6.2 C8.2 ; R6.2@969.69,540 1000,540 1025.79,565.79 U1.28
VOSNS: C16.1 R3.1 U1.9 | length 108
  Top Layer w10: U1.9 1259.21,565.79 1265.32,559.68 R3.1 C16.1
VOUT: Co1.1 Co2.1 Co3.1 Co4.1 J2.1 Q1.5 Q1.6 Q1.7 Q1.8 Q1.9 R2.2 R3.2 R18.1 TP2.1 | length 977
  Top Layer w8: R3.2 R18.1 1569.68,474.68 1600,505 1600,767.68 ; R2.2 1594.9,780.1 1600,775 1600,767.68 ; 1810,815 1810,785 1690,785 1672.68,767.68 1600,767.68
  other v2: 1520,1300 1580,1300 1635,1300 1520,1345 1580,1345 1635,1345 1520,1390 1580,1390 1635,1390
  other v3: 1525,990 1590,990
VRS: NT3.1 Q3.1 Q3.2 Q3.3 Q4.1 Q4.2 Q4.3 RS2.2 | length 25
  Signal Layer 2 w10: NT3.1 v1(1130,1175)
pads on no net: FID1.1 FID2.1 FID3.1

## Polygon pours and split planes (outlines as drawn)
VRS on Top Layer "Top Layer-VRS" (solid, remove dead copper, pour order 15): 805,1250 975,1250 975,1180 1035,1180 1035,1265 1180,1265 1231.57,1265 1236.57,1260 1246.57,1250 1385,1250 1385,1163.78 1366.22,1145 1361.22,1150 805,1150 805,1250
HDRV2_N on Top Layer "Top Layer-HDRV2_N" (solid, remove dead copper, pour order 14): 1230,1650 1685,1650 1685,1430 1680,1425 1530,1425 1530,1515 1480,1515 1480,1455.04 1464.96,1440 1455,1430.04 1455,1410 1455,1255 1236.57,1255 1235,1255 1230,1260 1230,1650
VIN on Top Layer "Top Layer-Vin" (solid, remove dead copper, pour order 13): 0,1800 0,1100 530,1100 530,950 750,950 800,1000 820,1000 820,1040 1035,1040 1035,1135 795,1135 795,1420 560,1420 560,1800 0,1800
GND on Top Layer "Top Layer-GND" (solid, remove dead copper, pour order 22): -5,1800 0,1795 0,0 2265,0 2260,5 2260,1800 -10,1800
VOUT on Top Layer "Top Layer-Vout" (solid, remove dead copper, pour order 18): 1470,1420 1470,1150 1225,1150 1220,1145 1215,1140 1215,1040 1494.37,1040 1495,1039.37 1495,945 1745,945 1745,800 2260,800 2260,1500 1750,1500 1740,1490 1740,1420 1464.96,1420
VIN on Bottom Layer "Bottom Layer-Vin" (solid, remove dead copper, pour order 16): 0,1800 500,1800 500,1450 750,1450 750,1175 900,1025 900,950 530,950 530,1100 0,1100 0,1800
VOUT on Bottom Layer "Top Layer-Vout" (solid, remove dead copper, pour order 20): 1485,1415 1485,1000 1465,1000 1435,970 1435,900 1745,900 1745,800 2260,800 2260,1500 1750,1500 1740,1490 1740,1420 1485,1420
GND on Bottom Layer "Bottom Layer-GND" (solid, remove dead copper, pour order 32): 0,1800 0,0 2260,0 2260,1800 0,1800
GND on Signal Layer 1 "Top Layer-GND" (solid, remove dead copper, pour order 23): -5,1800 0,1795 0,0 2260,0 2260,1800 -10,1800
GND on Signal Layer 2 "Signal Layer 1-GND" (solid, remove dead copper, pour order 30): -5,1800 0,1795 0,0 2260,0 2260,1800 0,1800

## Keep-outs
Keep-Out Layer:
  lines w10: -5,1800 -5,0 ; 0,1805 2260,1805 ; 2260,-5 0,-5 ; 2265,0 2265,1800 ; -5,0 ccw(c0,0) 0,-5 ; -5,0 ccw(c0,0) 0,-5 ; -5,3450 cw(c0,3450) 0,3455 ccw(c0,3450) -5,3450 ; 4950,-5 ccw(c4950,0) 4955,0 cw(c4950,0) 4950,-5 ; 4950,3455 cw(c4950,3450) 4955,3450 ccw(c4950,3450) 4950,3455
  text ".Layer_Name" at 577,-858.49 h60

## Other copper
Top Layer:
  rectangle net HDRV1_N: 630,1430 845,1525
  rectangle net HDRV1_N: 805,1260 1025,1650
  rectangle net VRS: 930,1145 1075,1165
  text ".Layer_Name" at 577,-858.49 h60
Bottom Layer:
  rectangle net HDRV1_N: 805,1250 1030,1650
  rectangle net HDRV2_N: 1230,1250 1433.43,1650
  text ".Layer_Name" at 577,-858.49 h60

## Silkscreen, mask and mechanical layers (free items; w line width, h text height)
Top Overlay:
  lines w10: 530,210 1730,210 1730,1650 530,1650 530,210
  text ".PRJ_Number" at 895,1700 h60
  text ".PCB_Rev" at 1495,1700 h60
  text ".Layer_Name" at 577,-858.49 h60
Bottom Overlay:
  text ".Layer_Name" at 577,-858.49 h60
Top Paste:
  text ".Layer_Name" at 577,-858.49 h60
Bottom Paste:
  text ".Layer_Name" at 577,-858.49 h60
Top Solder:
  text ".Layer_Name" at 577,-858.49 h60
  text ".Layer_Name" at 577,-858.49 h60
Bottom Solder:
  text ".Layer_Name" at 577,-858.49 h60
Drill Guide:
  text ".Layer_Name" at 577,-858.49 h60
M1 Board Outline:
  the board outline again, w10
  text ".Layer_Name" at 577,-858.49 h60
M2 Board Dimensions:
  rectangle: 0,-275 125,-150
  rectangle: 125,-400 500,-275
  lines w7: 0,-275 1000,-275 ; 125,-400 125,-150 ; 250,-400 250,-150 ; 500,-400 500,-150 ; 750,-400 750,-150 ; 0,-400 1000,-400 1000,-150 0,-150 0,-400
  text ".Layer_Name" at 577,-858.49 h60
M3 3D STEP Top:
  text ".Layer_Name" at 577,-858.49 h60
M4 3D STEP Bottom:
  text ".Layer_Name" at 577,-858.49 h60
M5 Assembly Top:
  lines w10: -292,-930.17 6308,-930.17 ; -292,-726.83 6310,-726.83 ; -292,-523.5 -292,-1133.5 3713,-1133.5 6310,-1133.5 6310,-523.5 -291.5,-523.5 -291.5,-1133.5 1284,-1133.5 ; 2173,-1133.5 2173,-523.5 ; 3440,-726.83 3440,-523.5 ; 4280,-726.83 4280,-523.5 ; 4902,-1140 4902,-937.17
  text "COMPONENTS MARKED 'DNP' SHOULD NOT BE POPULATED." at 1153.5,-318.5 h60
  text "ASSEMBLY VARIANT:" at 1153,-434 h60
  text ".VariantName" at 2189,-434 h60
  text "PCB VIEWED FROM TOP SIDE" at -228.5,-655.67 h60
  text "BOARD #:" at 2248,-655.67 h60
  text ".PRJ_Number" at 2793.5,-655.67 h60
  text "REV:" at 3638,-655.67 h60
  text ".PCB_Rev" at 3929.5,-655.67 h60
  text "SVN REV:" at 4476,-655.67 h60
  text ".VersionControl_RevNumber" at 4982,-655.67 h60
  text "TID #:" at 2248,-859 h60
  text ".TID" at 2793.5,-859 h60
  text "PLOT NAME =" at -228.5,-1064.34 h60
  text ".plot_File_Name" at 577,-1064.34 h60
  text "GENERATED    :" at 2250,-1064.34 h60
  text ".Print_Date" at 3119.5,-1064.34 h60
  text ".Print_Time" at 3848.5,-1064.34 h60
  text "TEXAS INSTRUMENTS" at 5113,-1064.34 h60
M6 Assembly Bottom:
  lines w10: -292.5,-727.33 6309.5,-727.33 ; -290.5,-930.67 6309.5,-930.67 ; 1115.5,-1140.5 1115.5,-937.67 ; 1737.5,-727.33 1737.5,-524 ; 2577.5,-727.33 2577.5,-524 ; 3844.5,-1134 3844.5,-524 ; 4733.5,-1134 6309,-1134 6309,-524 -292.5,-524 -292.5,-1134 2304.5,-1134 6309.5,-1134 6309.5,-524
  text "COMPONENTS MARKED 'DNP' SHOULD NOT BE POPULATED." at 6102,-318 h60
  text ".VariantName" at 5058,-434 h60
  text "ASSEMBLY VARIANT:" at 6097,-434 h60
  text ".VersionControl_RevNumber" at 1035.5,-656.17 h60
  text "SVN REV:" at 1541.5,-656.17 h60
  text ".PCB_Rev" at 2088,-656.17 h60
  text "REV:" at 2379.5,-656.17 h60
  text ".PRJ_Number" at 3224,-656.17 h60
  text "BOARD #:" at 3769.5,-656.17 h60
  text "PCB VIEWED FROM BOTTOM SIDE" at 6246,-656.17 h60
  text ".TID" at 3224,-859.5 h60
  text "TID #:" at 3769.5,-859.5 h60
  text "TEXAS INSTRUMENTS" at 904.5,-1064.84 h60
  text ".Print_Time" at 2169,-1064.84 h60
  text ".Print_Date" at 2898,-1064.84 h60
  text "GENERATED    :" at 3767.5,-1064.84 h60
  text ".plot_File_Name" at 5440.5,-1064.84 h60
  text "PLOT NAME =" at 6246,-1064.84 h60
M9 Title Sheet:
  drawing of 57 lines, arcs and shapes, not listed
  text "1" at 739.84,8036.5 h70
  text "2" at 3235.5,8036.5 h70
  text "3" at 5724.84,8036.5 h70
  text "4" at 8231.51,8036.5 h70
  text "5" at 10730.5,8036.5 h70
  text "6" at 13235.5,8036.5 h70
  text "A" at -416.5,6893.5 h70
  text "A" at 14383.5,6893.5 h70
  text "B" at -416.5,4513.5 h70
  text "B" at 14383.5,4513.5 h70
  text "C" at -416.5,2138.5 h70
  text "C" at 14383.5,2138.5 h70
  text "PROJECT TITLE:" at 11343.5,277.5 h45
  text ".PRJ_Title" at 11393.5,144.17 h70
  text "DESIGNED FOR:" at 11343.5,-23.5 h45
  text ".PRJ_Customer" at 11393.5,-163.5 h70
  text "D" at -416.5,-231.5 h70
  text "D" at 14383.5,-231.5 h70
  text "FILE NAME:" at 11343.5,-323.5 h45
  text ".PCB_File_Name_No_Path" at 11393.5,-443.5 h70
  text "Texas Instruments (TI) and/or its licensors do not warrant the accuracy or completeness of this specification" at 6374,-605.34 h45
  text "ENGINEER:" at 11343.5,-613.5 h45
  text "LAYOUT BY:" at 12848.5,-613.5 h45
  text "or any information contained therein. TI and/or its licensors do not warrant that this design will meet" at 6329.01,-718 h45
  text ".PRJ_Engineer" at 11393.5,-768.49 h70
  text ".PCB_Layout" at 12899,-768.49 h70
  text "the specifications, will be suitable for your application or fit for any particular purpose, or will operate in" at 6329.01,-830.67 h45
  text ".Layer_Name" at 577,-858.49 h60
  text "ALTIUM DESIGNER VERSION:" at 12848.5,-923.5 h45
  text "an implementation. TI and/or its licensors do not warrant that the design is production worthy. You should" at 6329.01,-943.33 h45
  text "completely validate and test your design implementation to confirm the system functionality for your application." at 6374,-1056 h45
  text ".print_Scale" at 11393.5,-1056.83 h70
  text ".Application_BuildNumber" at 12899,-1056.83 h70
  text "1" at 739.84,-1263.5 h70
  text "2" at 3235.5,-1263.5 h70
  text "3" at 5724.84,-1263.5 h70
  text "4" at 8231.51,-1263.5 h70
  text "5" at 10730.5,-1263.5 h70
  text "6" at 13235.5,-1263.5 h70
M10 Fab Notes:
  drawing of 173 lines, arcs and shapes, not listed
  text "DESIGN INFORMATION" at 12377.02,6201 h60
  text "MIN. TRACK WIDTH:" at 11732.46,6021 h60
  text "8" at 12828.7,6021 h60
  text "MIL" at 12983.46,6021 h60
  text "MIN. CLEARANCE:" at 11732.46,5889 h60
  text "0.2" at 12768.7,5889 h60
  text "mm" at 12983.46,5889 h60
  text "MIN. VIA PAD SIZE:" at 11732.46,5757 h60
  text "24" at 12798.71,5757 h60
  text "MIL" at 12983.46,5757 h60
  text "0.05mm (2MIL)" at 12427.46,5615.29 h60
  text "MINIMUM ANNULAR RING" at 11403.23,5611 h60
  text "EXTERNAL" at 13135.46,5611 h60
  text "PER" at 11603.23,5493 h60
  text "IPC-D-275 CLASS 2 LEVEL C" at 11823.23,5493 h60
  text "MIL, HOLES" at 13311.46,5380.71 h60
  text "+/-" at 12919,5380 h60
  text "+/-" at 13773,5380 h60
  text "REGISTRATION TOLERANCES:" at 11403.23,5375 h60
  text "METAL" at 12603,5375 h60
  text "5" at 13179.2,5375 h60
  text "3" at 14012.2,5375 h60
  text "MIL" at 14128.46,5375 h60
  text "+/-" at 13773,5262 h60
  text "HOLE SIZE TOLERANCE (UNLESS OTHERWISE SPECIFIED):" at 11403.23,5257 h60
  text "3" at 14012.2,5257 h60
  text "MIL" at 14128.46,5257 h60
  text "MATERIAL:" at 11328.46,5047.54 h60
  text "FR-4 High Tg" at 12314.9,4907.21 h60
  text "FR-408" at 11749.46,4898.64 h60
  text "OTHER" at 13237.46,4898.64 h60
  text "X" at 12160,4895 h60
  text "62 MIL (1.6mm) +/-10%" at 12069.56,4735.92 h60
  text "THICKNESS:" at 11403.23,4731.64 h60
  text "X" at 11941.4,4731.64 h60
  text "OTHER" at 13354.46,4731.64 h60
  text "TOLERANCE:" at 11403.23,4573.64 h60
  text "X" at 12242.53,4573.64 h60
  text "ANSI IPC-6012 TYPE 3 CLASS 2" at 12429.48,4573.64 h60
  text "OTHER +/-" at 12429.46,4417.64 h60
  text "BOW & TWIST:" at 11403.23,4260.64 h60
  text "X" at 12242.53,4260.64 h60
  text "ANSI IPC-6012 TYPE 3 CLASS 2" at 12429.48,4260.64 h60
  text "OTHER +/-" at 12429.46,4102.13 h60
  text "DRILLING:" at 11328.46,3963.64 h60
  text "REFERENCE:" at 11403.23,3846.64 h60
  text "X" at 12051.46,3846.64 h60
  text "AS SHOWN" at 12238.46,3846.64 h60
  text "X" at 12952.46,3846.64 h60
  text "NC_DRILL FILES" at 13089.46,3846.64 h60
  text "PTH MIN COPPER THICKNESS:" at 11403.23,3688.64 h60
  text "X" at 12753.46,3688.64 h60
  text "1MIL" at 12890.46,3688.64 h60
  text "OTHER" at 13387.46,3688.64 h60
  text "BOARD FINISH:" at 11328.46,3529.64 h60
  text "SILKSCREEN:" at 11483.68,3411.64 h60
  text "X" at 12432.46,3411.64 h60
  text "TOP" at 12558.46,3411.64 h60
  text "X" at 12942.46,3411.64 h60
  text "BOTTOM" at 13069.46,3411.64 h60
  text "SILKSCREEN COLOR:" at 11483.68,3244.64 h60
  text "X" at 12431.42,3244.64 h60
  text "WHITE" at 12558.46,3244.64 h60
  text "OTHER" at 13069.46,3244.64 h60
  text "X" at 12562.42,3085.44 h60
  text "GREEN" at 12689.46,3085.44 h60
  text "OTHER" at 13307.46,3085.44 h60
  text "SOLDER RESIST COLOR:" at 11483.68,3074.64 h60
  text "X" at 12562.42,2915.44 h60
  text "MATTE" at 12689.46,2915.44 h60
  text "SEMI-GLOSS" at 13307,2914.8 h60
  text "IMMERSION GOLD (ENIG)" at 12389.46,2726.92 h60
  text "ENEPIG" at 13727,2723.64 h60
  text "SURFACE FINISH:" at 11328.46,2722.64 h60
  text "X" at 12202.51,2722.64 h60
  text "IMM. TIN/SILVER OR EQUIV" at 11658,2565.64 h60
  text "OTHER" at 13089.46,2565.64 h60
  text "ARRAY/PANEL:" at 11328.46,2386.64 h60
  text "CUT AND TRIM PER M1 BOARD OUTLINE" at 12389.46,2382.35 h60
  text "N.C. ROUTE" at 12389.46,2230.64 h60
  text "X" at 13068.46,2230.64 h60
  text "V. SCORE" at 13255.46,2230.64 h60
  text "CERTIFICATION:" at 11328.46,2093.64 h60
  text "MATERIALS AND WORKMANSHIP FOR ALL PCBS" at 12053.46,2093.64 h60
  text "TO MEET OR EXCEED THE REQUIREMENTS OF:" at 12053.46,1995.64 h60
  text "X" at 11679.96,1859.13 h60
  text "ANSI IPC-A-600F CLASS ->" at 11818.96,1859.13 h60
  text "X" at 13458.02,1859.13 h60
  text "2" at 13576.96,1859.14 h60
  text "1" at 13261.96,1857.64 h60
  text "3" at 13930.96,1857.64 h60
  text "X" at 12494.02,1699.64 h60
  text "RoHS" at 12630.96,1699.64 h60
  text "OTHER" at 13275.36,1699.64 h60
  text "PER ORDER" at 13672.42,1699.64 h60
  text "ALL BOARDS MUST MEET OR EXCEED UL94-V0 REQUIREMENTS." at 11356,1534 h60
  text "PCB MUST BEAR THE UL94V-0 UL REGISTERED MATERIAL ID NUMBER" at 11356,1414 h60
  text "ADDITIONAL REQUIREMENTS:" at 11328.46,1240.64 h60
  text "MICROSECTION:" at 11403.23,1125.64 h60
  text "YES" at 12308.96,1125.64 h60
  text "REQUIRED" at 13170.46,969.49 h60
  text "BARE BOARD ELEC. TEST:" at 11403.23,966.64 h60
  text "NONE" at 12708.96,966.64 h60
  text "X" at 13043.46,966.64 h60
  text "PER ORDER" at 13762.46,966.64 h60
  text ".Layer_Name" at 577,-858.49 h60
M11 Gerber Information:
  lines w10: -292,-930.17 6308,-930.17 ; -292,-726.83 6310,-726.83 ; -292,-523.5 -292,-1133.5 3713,-1133.5 6310,-1133.5 6310,-523.5 -291.5,-523.5 -291.5,-1133.5 1284,-1133.5 ; 2173,-1133.5 2173,-523.5 ; 3440,-726.83 3440,-523.5 ; 4280,-726.83 4280,-523.5 ; 4902,-1140 4902,-937.17
  text "ALL ARTWORK VIEWED FROM TOP SIDE" at -228.5,-655.67 h60
  text "BOARD #:" at 2248,-655.67 h60
  text ".PRJ_Number" at 2793.5,-655.67 h60
  text "REV:" at 3638,-655.67 h60
  text ".PCB_Rev" at 3929.5,-655.67 h60
  text "SVN REV:" at 4476,-655.67 h60
  text ".VersionControl_RevNumber" at 4982,-655.67 h60
  text "LAYER NAME =" at -228.5,-858.49 h60
  text "TID #:" at 2248,-859 h60
  text ".TID" at 2793.5,-859 h60
  text "PLOT NAME =" at -228.5,-1064.34 h60
  text ".plot_File_Name" at 577,-1064.34 h60
  text "GENERATED    :" at 2250,-1064.34 h60
  text ".Print_Date" at 3119.5,-1064.34 h60
  text ".Print_Time" at 3848.5,-1064.34 h60
  text "TEXAS INSTRUMENTS" at 5113,-1064.34 h60
M12 Stackup:
  drawing of 295 lines, arcs and shapes, not listed
  text "Layer" at 6505.58,7445 h60
  text "Name" at 6915.49,7445 h60
  text "Material" at 7855.23,7445 h60
  text "Thickness" at 8715,7445 h60
  text "Constant" at 9364.84,7445 h60
  text "Board Layer Stack" at 9934.7,7445 h60
  text "1" at 6505.58,7325 h60
  text "Top Overlay" at 6915.49,7325 h60
  text "2" at 6505.58,7205 h60
  text "Top Solder" at 6915.49,7205 h60
  text "Solder Resist" at 7855.23,7205 h60
  text "0.40mil" at 8715,7205 h60
  text "3.5" at 9364.84,7205 h60
  text "3" at 6505.58,7085 h60
  text "Top Layer" at 6915.49,7085 h60
  text "Copper" at 7855.23,7085 h60
  text "2.80mil" at 8715,7085 h60
  text "4" at 6505.58,6965 h60
  text "Dielectric1" at 6915.49,6965 h60
  text "FR-4" at 7855.23,6965 h60
  text "20.00mil" at 8715,6965 h60
  text "4.8" at 9364.84,6965 h60
  text "5" at 6505.58,6845 h60
  text "Signal Layer 1" at 6915.49,6845 h60
  text "Copper" at 7855.23,6845 h60
  text "1.40mil" at 8715,6845 h60
  text "6" at 6505.58,6725 h60
  text "Dielectric 2" at 6915.49,6725 h60
  text "12.80mil" at 8715,6725 h60
  text "4.2" at 9364.84,6725 h60
  text "7" at 6505.58,6605 h60
  text "Signal Layer 2" at 6915.49,6605 h60
  text "Copper" at 7855.23,6605 h60
  text "1.40mil" at 8715,6605 h60
  text "8" at 6505.58,6485 h60
  text "Dielectric 3" at 6915.49,6485 h60
  text "FR-4" at 7855.23,6485 h60
  text "20.00mil" at 8715,6485 h60
  text "4.8" at 9364.84,6485 h60
  text "9" at 6505.58,6365 h60
  text "Bottom Layer" at 6915.49,6365 h60
  text "Copper" at 7855.23,6365 h60
  text "2.80mil" at 8715,6365 h60
  text "10" at 6505.58,6245 h60
  text "Bottom Solder" at 6915.49,6245 h60
  text "Solder Resist" at 7855.23,6245 h60
  text "0.40mil" at 8715,6245 h60
  text "3.5" at 9364.84,6245 h60
  text "11" at 6505.58,6125 h60
  text "Bottom Overlay" at 6915.49,6125 h60
  text ".Layer_Name" at 577,-858.49 h60
M13 Component Bodies Top:
  text ".Layer_Name" at 577,-858.49 h60
M14 Component Bodies Bottom:
  text ".Layer_Name" at 577,-858.49 h60
M15 Courtyards Top:
  text ".Layer_Name" at 577,-858.49 h60
M16 Courtyards Bottom:
  text ".Layer_Name" at 577,-858.49 h60
Drill Drawing:
  lines w1: 3047.89,598.09 3047.89,610.54 3060.35,623 3047.89,635.45 3047.89,647.91 3060.35,647.91 3072.8,635.45 3085.26,647.91 3097.71,647.91 3097.71,635.45 3085.26,623 3097.71,610.54 3097.71,598.09 3085.26,598.09 3072.8,610.54 3060.35,598.09 3047.89,598.09 ; 3047.89,760 3060.35,760 3072.8,747.54 3085.26,760 3097.71,760 3085.26,772.45 3097.71,784.91 3085.26,784.91 3072.8,797.36 3060.35,784.91 3047.89,784.91 3060.35,772.45 3047.89,760 ; 3047.89,946.82 3097.71,946.82 3072.8,897 3047.89,946.82 ; 3047.89,1071.37 3072.8,1046.46 3097.71,1071.37 3072.8,1096.28 3047.89,1071.37 ; 3047.89,1208.38 3060.35,1208.38 3060.35,1195.92 3085.26,1195.92 3085.26,1208.38 3097.71,1208.38 3097.71,1233.28 3085.26,1233.28 3085.26,1245.74 3060.35,1245.74 3060.35,1233.28 3047.89,1233.28 3047.89,1208.38
  lines w12: 2980,553.25 5099.4,553.25 ; 2980,1300.54 5099.4,1300.54 ; 3350.67,403.79 3350.67,1450 ; 3707.78,403.79 3707.78,1450 ; 4369.79,403.79 4369.79,1450 ; 4654.14,403.79 4654.14,1450 ; 2980,403.79 5099.4,403.79 5099.4,1450 2980,1450 2980,403.79
  text "Symbol" at 3069.68,1345.38 h72
  text "Quantity" at 3395.51,1345.38 h72
  text "Finished Hole Size" at 3752.62,1345.38 h72
  text "Plated" at 4414.62,1345.38 h72
  text "Hole Type" at 4698.98,1345.38 h72
  text "39" at 3395.51,1195.92 h60
  text "10.00mil (0.254mm)" at 3752.62,1195.92 h60
  text "PTH" at 4414.62,1195.92 h60
  text "Round" at 4698.98,1195.92 h60
  text "46" at 3395.51,1046.46 h60
  text "20.00mil (0.508mm)" at 3752.62,1046.46 h60
  text "PTH" at 4414.62,1046.46 h60
  text "Round" at 4698.98,1046.46 h60
  text "11" at 3395.51,897 h60
  text "40.00mil (1.016mm)" at 3752.62,897 h60
  text "PTH" at 4414.62,897 h60
  text "Round" at 4698.98,897 h60
  text "2" at 3395.51,747.54 h60
  text "98.43mil (2.500mm)" at 3752.62,747.54 h60
  text "PTH" at 4414.62,747.54 h60
  text "Round" at 4698.98,747.54 h60
  text "4" at 3395.51,598.09 h60
  text "214.57mil (5.450mm)" at 3752.62,598.09 h60
  text "PTH" at 4414.62,598.09 h60
  text "Round" at 4698.98,598.09 h60
  text "102 Total" at 3395.51,448.63 h60
  text ".Layer_Name" at 577,-858.49 h60

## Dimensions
0,-400 to 1000,-400 on M2 Board Dimensions
0,0 to 0,1800 on M2 Board Dimensions
0,0 to 2260,0 on M2 Board Dimensions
